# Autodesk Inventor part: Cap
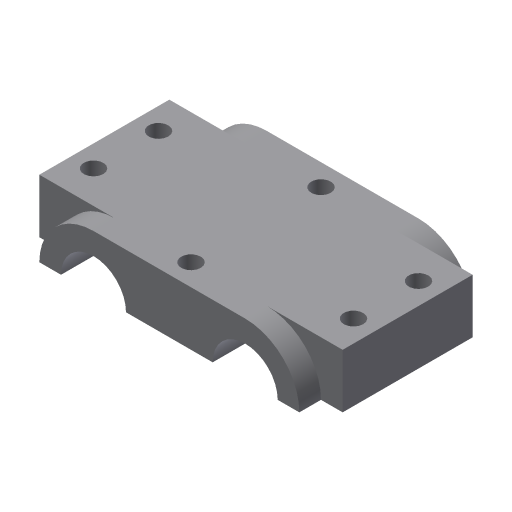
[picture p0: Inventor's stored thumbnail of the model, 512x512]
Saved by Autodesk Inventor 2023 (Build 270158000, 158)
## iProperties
Shininess: 77.0
Length Units: 11269
Angle Units: 11279
Time Units: 11290
Mass Units: 11283
Length Display Precision: 3
Angle Display Precision: 2
Created: 2002-02
Part Number: Cap
Document SubType Name: Modeling
Designer: ***
Density: 1 g/cm^3
Material: Generic
Appearance: Default
Density: 0.0
Volumn: 0.0
Area: 0.0
PropertySet Name: Model Information
Control State: 0
Master: False
Checked Out: False
Author: ***
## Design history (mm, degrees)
sketch "Sketch2"
  geometry: L1 (-17.5, 12.5)-(17.5, 12.5); L2 (30, 0)-(25, 0); L3 (10, 0)-(-10, 0); L4 (-25, 0)-(-30, 0); A1 r 12.5 centre (-17.5, 0) between (-17.5, 12.5) and (-30, 0); A2 r 12.5 centre (17.5, 0) between (30, 0) and (17.5, 12.5); A3 r 7.5 centre (17.5, 0) between (25, 0) and (10, 0); A4 r 7.5 centre (-17.5, 0) between (-10, 0) and (-25, 0)
  constraints: 8 end point, 8 point on circle, 4 centre point, 3 horizontal, 3 parallel, 2 coincident, 2 equal radius, 2 tangent
  dimensions: "d0" = 12.5 radius of A1; "d1" = 7.5 radius of A4; "d2" = 35 distance of A1.centre A2.centre; "d3" = 12.5 distance between parallel lines of L1 L3
extrude "Extrusion1" new body sketch "Sketch2" stored distance "d4" = 40; taper "d5" = 0 deg
workplane "Work Plane1"
sketch "Sketch3"
  geometry: L1 (-15, 12.5)-(15, 12.5); L2 (15, 12.5)-(15, 0); L3 (15, 0)-(-15, 0); L4 (-15, 0)-(-15, 12.5); L5 (-20, 0)-(20, 0) reference; L6 (-20, 12.5)-(20, 12.5) reference; L7 (20, 12.5)-(20, 0) reference
  constraints: 8 end point, 2 collinear, 2 parallel, 1 horizontal, 1 perpendicular
  dimensions: "d7" = 30 distance of L2.end L3.end; "d8" = 5 distance between parallel lines of L7 L2
extrude "Extrusion2" join sketch "Sketch3" stored distance "d9" = 40; taper "d10" = 0 deg
mirror "Mirror1"
sketch "Sketch4"
  geometry: L1 (-17.5, -35)-(0, -35) reference; L2 (-17.5, -35)-(-17.5, -5) reference; 1 further point
  dimensions: "d12" = 7.5 distance from line of L1 point (-12.5, -27.5); "d13" = 5 distance from line of L2 point (-12.5, -27.5)
hole "Hole1" sketch "Sketch4" at (-12.5, -27.5) diameter "d14" = 4.5; stored, may be unused: countersink angle "d18" = 82 deg, drill point angle "d20" = 118 deg; dims "d15" = 6, "d16" = 4, "d17" = 2, "d19" = 8
pattern_linear "Rectangular Pattern1" dims "d23" = 60, "d26" = 15
sketch "Sketch5"
  geometry: L1 (0, -40)-(35, -40) reference; L2 (-17.5, -35)-(-17.5, -5) reference; 1 further point
  dimensions: "d27" = 5 distance from line of L1 point (17.5, -35); "d28" = 35 distance from line of L2 point (17.5, -35)
hole "Hole2" sketch "Sketch5" at (17.5, -35) diameter "d29" = 4.5; stored, may be unused: countersink angle "d33" = 82 deg, drill point angle "d35" = 118 deg; dims "d30" = 6, "d31" = 4, "d32" = 2, "d34" = 8
pattern_linear "Rectangular Pattern2" dims "d38" = 30
body "Solid1"
other parameters: "d11" = 35
